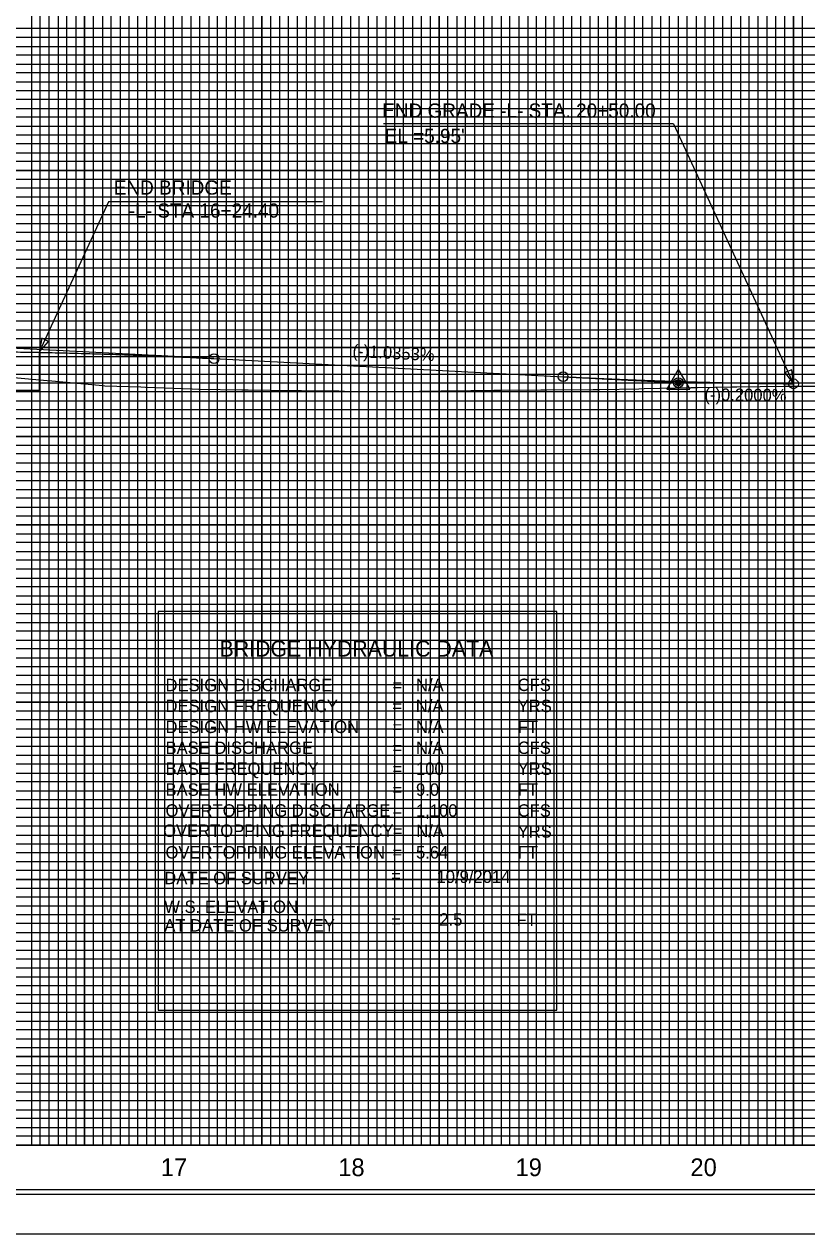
# Model space of a CAD drawing. Extents: x 575424 to 577182, y -52702 to -51602.
# Drawn here: x 576331 to 576773, y -52702 to -52020 of the extents above; entities that cross this region are included whole.
import ezdxf

# ---------------------------------------------------------------- set-up
doc = ezdxf.new("R2010")
doc.units = 0
for name, color, linetype in [('Exist Profile Cell', 7, 'Continuous'), ('Exist Vertical Profile Ground Line', 7, 'Continuous'), ('Exist Vertical Profile Horizontal Axis Label Major', 7, 'Continuous'), ('Prop Grid Mask', 7, 'Continuous'), ('Prop PFL Structure Hydraulic Data Label CELL', 7, 'Continuous'), ('Prop PFL VPI Symbol CELL', 7, 'Continuous'), ('Prop Roadway Bridge', 7, 'Continuous'), ('Prop Vertical Profile Curve Label', 7, 'Continuous'), ('Prop Vertical Profile Ditch Grade Right Label', 7, 'Continuous'), ('Prop Vertical Profile Grade', 7, 'Continuous'), ('Prop Vertical Profile Grade Label', 7, 'Continuous'), ('Prop VPI Label', 7, 'Continuous'), ('Scratch_Level_1', 7, 'Continuous'), ('Sheet Cutting Line CELL', 7, 'Continuous'), ('Sheet DOT Grid CELL', 7, 'Continuous'), ('Sheet Layout Profile Border', 7, 'Continuous'), ('Sheet Plot Border Inside CELL', 7, 'Continuous'), ('Sheet Plot Border Outside CELL', 7, 'Continuous'), ('Sheet Profile CELL', 7, 'Continuous'), ('Sheet Profile Grid Major CELL', 7, 'Continuous'), ('Sheet Profile Grid Middle CELL', 7, 'Continuous'), ('Sheet Profile Grid Minor CELL', 7, 'Continuous')]:
    doc.layers.add(name, color=color, linetype=linetype)

# ---------------------------------------------------------------- blocks, each defined once
blk = doc.blocks.new('Profile VPI Symbol')
at = {"layer": 'Prop PFL VPI Symbol CELL'}
for p, q in [((-0.001, 0.147), (-0.13, -0.077)), ((-0.001, 0.147), (0.129, -0.077)), ((-0.13, -0.077), (0.129, -0.077))]:
    blk.add_line(p, q, dxfattribs=at)
for radius in [0.035, 0.024]:
    blk.add_circle((-0.001, -0.003), radius, dxfattribs=at)

msp = doc.modelspace()

# ---------------------------------------------------------------- linework, layer by layer
at = {"layer": 'Exist Profile Cell'}
msp.add_line((575715.21, -52252.64), (576835.62, -52252.64), dxfattribs=at)
at = {"layer": 'Exist Vertical Profile Ground Line'}
msp.add_lwpolyline([(576320.86, -52218.9), (576344.06, -52221.01), (576346.72, -52221.24), (576373.5, -52223.72), (576376.71, -52224), (576396.98, -52224.67), (576399.6, -52224.8), (576425.87, -52225.66), (576429.6, -52225.85), (576453.87, -52226.28), (576457.56, -52226.27), (576483.52, -52226.74), (576487.56, -52226.72), (576508.6, -52226.9), (576511.77, -52226.96), (576537.83, -52227.18), (576541.77, -52227.24), (576566.33, -52226.88), (576569.94, -52226.84), (576596.12, -52226.45), (576599.94, -52226.4), (576622.54, -52226.27), (576626, -52226.26), (576652.11, -52226.11), (576656, -52226.1), (576677.86, -52225.65), (576680.97, -52225.56), (576707.18, -52225.02), (576710.97, -52224.9), (576730.38, -52224.61), (576733.22, -52224.58), (576759.5, -52224.19), (576763.22, -52224.14), (576788.07, -52224.25)], dxfattribs=at)
at = {"layer": 'Prop Grid Mask'}
msp.add_lwpolyline([(576406.66, -52576.39), (576631.66, -52576.39), (576631.66, -52351.39), (576406.66, -52351.39)], close=True, dxfattribs=at)
at = {"layer": 'Prop Roadway Bridge'}
for p in [(576339.61, -52205.1), (576219.61, -52226.45)]:
    msp.add_line(p, (576339.61, -52226.45), dxfattribs=at)
at = {"layer": 'Prop Vertical Profile Grade'}
msp.add_line((576438.21, -52208.68), (576635.21, -52218.88), dxfattribs=at)
for points in [[(576112.21, -52209), (576118.73, -52208.66), (576125.25, -52208.33), (576131.77, -52208.01), (576138.29, -52207.71), (576144.81, -52207.42), (576151.33, -52207.15), (576157.85, -52206.88), (576164.37, -52206.64), (576170.89, -52206.4), (576177.41, -52206.18), (576183.93, -52205.98), (576190.45, -52205.79), (576196.97, -52205.61), (576203.49, -52205.44), (576210.01, -52205.29), (576216.53, -52205.16), (576223.05, -52205.03), (576229.57, -52204.92), (576236.09, -52204.83), (576242.61, -52204.74), (576249.13, -52204.68), (576255.65, -52204.62), (576262.17, -52204.58), (576268.69, -52204.55), (576275.21, -52204.54), (576281.73, -52204.54), (576288.25, -52204.55), (576294.77, -52204.58), (576301.29, -52204.62), (576307.81, -52204.68), (576314.33, -52204.75), (576320.85, -52204.83), (576327.37, -52204.93), (576333.89, -52205.04), (576340.41, -52205.16), (576346.93, -52205.3), (576353.45, -52205.45), (576359.97, -52205.62), (576366.49, -52205.8), (576373.01, -52205.99), (576379.53, -52206.2), (576386.05, -52206.42), (576392.57, -52206.65), (576399.09, -52206.9), (576405.61, -52207.16), (576412.13, -52207.44), (576418.65, -52207.73), (576425.17, -52208.03), (576431.69, -52208.35), (576438.21, -52208.68)], [(576635.21, -52218.88), (576637.81, -52219.01), (576640.41, -52219.14), (576643.01, -52219.27), (576645.61, -52219.4), (576648.21, -52219.52), (576650.81, -52219.64), (576653.41, -52219.76), (576656.01, -52219.88), (576658.61, -52220), (576661.21, -52220.11), (576663.81, -52220.22), (576666.41, -52220.33), (576669.01, -52220.44), (576671.61, -52220.55), (576674.21, -52220.65), (576676.81, -52220.75), (576679.41, -52220.85), (576682.01, -52220.95), (576684.61, -52221.04), (576687.21, -52221.13), (576689.81, -52221.22), (576692.41, -52221.31), (576695.01, -52221.4), (576697.61, -52221.48), (576700.21, -52221.56), (576702.81, -52221.64), (576705.41, -52221.72), (576708.01, -52221.79), (576710.61, -52221.87), (576713.21, -52221.94), (576715.81, -52222), (576718.41, -52222.07), (576721.01, -52222.13), (576723.61, -52222.2), (576726.21, -52222.26), (576728.81, -52222.31), (576731.41, -52222.37), (576734.01, -52222.42), (576736.61, -52222.47), (576739.21, -52222.52), (576741.81, -52222.57), (576744.41, -52222.61), (576747.01, -52222.65), (576749.61, -52222.7), (576752.21, -52222.73), (576754.81, -52222.77), (576757.41, -52222.8), (576760.01, -52222.83), (576762.61, -52222.86), (576765.21, -52222.89)]]:
    msp.add_spline(points, degree=3, dxfattribs=at)
at = {"layer": 'Prop Vertical Profile Grade Label'}
for p, q in [((576697.41, -52076.2), (576533.9, -52076.2)), ((576499.49, -52120.15), (576378.62, -52120.15))]:
    msp.add_line(p, q, dxfattribs=at)
for points in [[(576697.41, -52076.2), (576765.21, -52222.9)], [(576378.62, -52120.15), (576339.61, -52205.1)]]:
    msp.add_lwpolyline(points, dxfattribs=at)
for points in [[(576340.98, -52197.22), (576339.61, -52205.1), (576344.74, -52198.96)], [(576760.35, -52216.55), (576765.21, -52222.9), (576764.18, -52214.97)]]:
    msp.add_lwpolyline(points, close=True, dxfattribs=at)
at = {"layer": 'Prop VPI Label'}
for p, q in [((576438.21, -52208.68), (576277.96, -52200.38)), ((576635.21, -52218.88), (576697.46, -52222.1)), ((576765.21, -52222.89), (576702.96, -52222.27))]:
    msp.add_line(p, q, dxfattribs=at)
for centre in [(576438.21, -52208.68), (576635.21, -52218.88), (576700.21, -52222.24), (576765.21, -52222.9)]:
    msp.add_circle(centre, 2.75, dxfattribs=at)
at = {"layer": 'Scratch_Level_1'}
msp.add_line((576996.24, -52212.64), (575674.58, -52212.64), dxfattribs=at)
at = {"layer": 'Sheet Cutting Line CELL'}
msp.add_line((575498.21, -52702.49), (577182.21, -52702.49), dxfattribs=at)
at = {"layer": 'Sheet DOT Grid CELL'}
for p, q in [((576365.21, -51627.49), (576365.21, -52652.49)), ((576415.21, -51627.49), (576415.21, -52652.49)), ((576465.21, -51627.49), (576465.21, -52652.49)), ((576515.21, -51627.49), (576515.21, -52652.49)), ((576565.21, -51627.49), (576565.21, -52652.49)), ((576615.21, -51627.49), (576615.21, -52652.49)), ((576665.21, -51627.49), (576665.21, -52652.49)), ((576715.21, -51627.49), (576715.21, -52652.49)), ((576765.21, -51627.49), (576765.21, -52652.49)), ((575665.21, -52052.49), (577165.21, -52052.49)), ((575665.21, -52102.49), (577165.21, -52102.49)), ((575665.21, -52152.49), (577165.21, -52152.49)), ((575665.21, -52202.49), (577165.21, -52202.49)), ((575665.21, -52252.49), (577165.21, -52252.49)), ((575665.21, -52302.49), (577165.21, -52302.49)), ((575665.21, -52352.49), (577165.21, -52352.49)), ((575665.21, -52402.49), (577165.21, -52402.49)), ((575665.21, -52452.49), (577165.21, -52452.49)), ((575665.21, -52502.49), (577165.21, -52502.49)), ((575665.21, -52552.49), (577165.21, -52552.49)), ((575665.21, -52602.49), (577165.21, -52602.49))]:
    msp.add_line(p, q, dxfattribs=at)
at = {"layer": 'Sheet Layout Profile Border'}
msp.add_lwpolyline([(575715.21, -51627.49), (575715.21, -52652.49), (577115.21, -52652.49), (577115.21, -51765.04), (576965.16, -51765.04), (576965.16, -51627.49)], close=True, dxfattribs=at)
at = {"layer": 'Sheet Plot Border Inside CELL'}
msp.add_lwpolyline([(577177.71, -51624.94), (575511.21, -51624.94), (575511.21, -52680.04), (577177.71, -52680.04)], close=True, dxfattribs=at)
at = {"layer": 'Sheet Plot Border Outside CELL'}
msp.add_lwpolyline([(577182.21, -51602.49), (575498.21, -51602.49), (575498.21, -52702.49), (577182.21, -52702.49)], close=True, dxfattribs=at)
at = {"layer": 'Sheet Profile CELL'}
msp.add_line((577165.21, -52652.49), (575665.21, -52652.49), dxfattribs=at)
msp.add_lwpolyline([(577165.21, -51627.49), (575665.21, -51627.49), (575665.21, -52677.49), (577165.21, -52677.49)], close=True, dxfattribs=at)
at = {"layer": 'Sheet Profile Grid Major CELL'}
for points in [[(576315.21, -52652.49), (576365.21, -52652.49), (576365.21, -51627.49)], [(576415.21, -51627.49), (576415.21, -52652.49), (576465.21, -52652.49), (576465.21, -51627.49)], [(576515.21, -51627.49), (576515.21, -52652.49), (576565.21, -52652.49), (576565.21, -51627.49)], [(576615.21, -51627.49), (576615.21, -52652.49), (576665.21, -52652.49), (576665.21, -51627.49)], [(576715.21, -51627.49), (576715.21, -52652.49), (576765.21, -52652.49), (576765.21, -51627.49)], [(577165.21, -52102.49), (575665.21, -52102.49), (575665.21, -52052.49), (577165.21, -52052.49)], [(577165.21, -52202.49), (575665.21, -52202.49), (575665.21, -52152.49), (577165.21, -52152.49)], [(577165.21, -52302.49), (575665.21, -52302.49), (575665.21, -52252.49), (577165.21, -52252.49)], [(577165.21, -52402.49), (575665.21, -52402.49), (575665.21, -52352.49), (577165.21, -52352.49)], [(577165.21, -52502.49), (575665.21, -52502.49), (575665.21, -52452.49), (577165.21, -52452.49)], [(577165.21, -52602.49), (575665.21, -52602.49), (575665.21, -52552.49), (577165.21, -52552.49)]]:
    msp.add_lwpolyline(points, dxfattribs=at)
at = {"layer": 'Sheet Profile Grid Middle CELL'}
for points in [[(576290.21, -52652.49), (576340.21, -52652.49), (576340.21, -51627.49)], [(576390.21, -51627.49), (576390.21, -52652.49), (576440.21, -52652.49), (576440.21, -51627.49)], [(576490.21, -51627.49), (576490.21, -52652.49), (576540.21, -52652.49), (576540.21, -51627.49)], [(576590.21, -51627.49), (576590.21, -52652.49), (576640.21, -52652.49), (576640.21, -51627.49)], [(576690.21, -51627.49), (576690.21, -52652.49), (576740.21, -52652.49), (576740.21, -51627.49)], [(577165.21, -52027.49), (575665.21, -52027.49), (575665.21, -52077.49), (577165.21, -52077.49)], [(577165.21, -52127.49), (575665.21, -52127.49), (575665.21, -52177.49), (577165.21, -52177.49)], [(577165.21, -52227.49), (575665.21, -52227.49), (575665.21, -52277.49), (577165.21, -52277.49)], [(577165.21, -52327.49), (575665.21, -52327.49), (575665.21, -52377.49), (577165.21, -52377.49)], [(577165.21, -52427.49), (575665.21, -52427.49), (575665.21, -52477.49), (577165.21, -52477.49)], [(577165.21, -52527.49), (575665.21, -52527.49), (575665.21, -52577.49), (577165.21, -52577.49)], [(577165.21, -52627.49), (575665.21, -52627.49)]]:
    msp.add_lwpolyline(points, dxfattribs=at)
at = {"layer": 'Sheet Profile Grid Minor CELL'}
for points in [[(576335.21, -51627.49), (576335.21, -52652.49), (576345.21, -52652.49), (576345.21, -51627.49)], [(576350.21, -51627.49), (576350.21, -52652.49), (576355.21, -52652.49), (576355.21, -51627.49)], [(576360.21, -51627.49), (576360.21, -52652.49), (576370.21, -52652.49), (576370.21, -51627.49)], [(576375.21, -51627.49), (576375.21, -52652.49), (576380.21, -52652.49), (576380.21, -51627.49)], [(576385.21, -51627.49), (576385.21, -52652.49), (576395.21, -52652.49), (576395.21, -51627.49)], [(576400.21, -51627.49), (576400.21, -52652.49), (576405.21, -52652.49), (576405.21, -51627.49)], [(576410.21, -51627.49), (576410.21, -52652.49), (576420.21, -52652.49), (576420.21, -51627.49)], [(576425.21, -51627.49), (576425.21, -52652.49)], [(576425.21, -52652.49), (576430.21, -52652.49), (576430.21, -51628.09)], [(576435.21, -51628.09), (576435.21, -52652.49), (576445.21, -52652.49), (576445.21, -51627.49)], [(576450.21, -51627.49), (576450.21, -52652.49), (576455.21, -52652.49), (576455.21, -51627.49)], [(576460.21, -51627.49), (576460.21, -52652.49), (576470.21, -52652.49), (576470.21, -51627.49)], [(576475.21, -51627.49), (576475.21, -52652.49), (576480.21, -52652.49), (576480.21, -51627.49)], [(576485.21, -51627.49), (576485.21, -52652.49), (576495.21, -52652.49), (576495.21, -51627.49)], [(576500.21, -51627.49), (576500.21, -52652.49), (576505.21, -52652.49), (576505.21, -51627.49)], [(576510.21, -51627.49), (576510.21, -52652.49), (576520.21, -52652.49), (576520.21, -51627.49)], [(576525.21, -51627.49), (576525.21, -52652.49), (576530.21, -52652.49), (576530.21, -51627.49)], [(576535.21, -51627.49), (576535.21, -52652.49), (576545.21, -52652.49), (576545.21, -51627.49)], [(576550.21, -51627.49), (576550.21, -52652.49), (576555.21, -52652.49), (576555.21, -51627.49)], [(576560.21, -51627.49), (576560.21, -52652.49), (576570.21, -52652.49), (576570.21, -51627.49)], [(576575.21, -51627.49), (576575.21, -52652.49), (576580.21, -52652.49), (576580.21, -51627.49)], [(576585.21, -51627.49), (576585.21, -52652.49), (576595.21, -52652.49), (576595.21, -51627.49)], [(576600.21, -51627.49), (576600.21, -52652.49), (576605.21, -52652.49), (576605.21, -51627.49)], [(576610.21, -51627.49), (576610.21, -52652.49), (576620.21, -52652.49), (576620.21, -51627.49)], [(576625.21, -51627.49), (576625.21, -52652.49), (576630.21, -52652.49), (576630.21, -51627.49)], [(576635.21, -51627.49), (576635.21, -52652.49), (576645.21, -52652.49), (576645.21, -51627.49)], [(576650.21, -51627.49), (576650.21, -52652.49), (576655.21, -52652.49), (576655.21, -51627.49)], [(576660.21, -51627.49), (576660.21, -52652.49), (576670.21, -52652.49), (576670.21, -51627.49)], [(576675.21, -51627.49), (576675.21, -52652.49), (576680.21, -52652.49), (576680.21, -51627.49)], [(576685.21, -51627.49), (576685.21, -52652.49), (576695.21, -52652.49), (576695.21, -51627.49)], [(576700.21, -51627.49), (576700.21, -52652.49), (576705.21, -52652.49), (576705.21, -51627.49)], [(576710.21, -51627.49), (576710.21, -52652.49), (576720.21, -52652.49), (576720.21, -51627.49)], [(576725.21, -51627.49), (576725.21, -52652.49), (576730.21, -52652.49), (576730.21, -51627.49)], [(576735.21, -51627.49), (576735.21, -52652.49)], [(576735.21, -52652.49), (576745.21, -52652.49), (576745.21, -51627.49)], [(576750.21, -51627.49), (576750.21, -52652.49), (576755.21, -52652.49), (576755.21, -51627.49)], [(576760.21, -51627.49), (576760.21, -52652.49), (576770.21, -52652.49), (576770.21, -51627.49)], [(577115.21, -52022.49), (575715.21, -52022.49), (575715.21, -52032.49), (577115.21, -52032.49)], [(577115.21, -52037.49), (575715.21, -52037.49), (575715.21, -52042.49), (577115.21, -52042.49)], [(577115.21, -52047.49), (575715.21, -52047.49), (575715.21, -52057.49), (577115.21, -52057.49)], [(577115.21, -52062.49), (575715.21, -52062.49), (575715.21, -52067.49), (577115.21, -52067.49)], [(577115.21, -52072.49), (575715.21, -52072.49), (575715.21, -52082.49), (577115.21, -52082.49)], [(577115.21, -52087.49), (575715.21, -52087.49), (575715.21, -52092.49), (577115.21, -52092.49)], [(577115.21, -52097.49), (575715.21, -52097.49), (575715.21, -52107.49), (577115.21, -52107.49)], [(577115.21, -52112.49), (575715.21, -52112.49), (575715.21, -52117.49), (577115.21, -52117.49)], [(577115.21, -52122.49), (575715.21, -52122.49), (575715.21, -52132.49), (577115.21, -52132.49)], [(577115.21, -52137.49), (575715.21, -52137.49), (575715.21, -52142.49), (577115.21, -52142.49)], [(577115.21, -52147.49), (575715.21, -52147.49)], [(575715.21, -52157.49), (577115.21, -52157.49)], [(577115.21, -52162.49), (575715.21, -52162.49), (575715.21, -52167.49), (577115.21, -52167.49)], [(577115.21, -52172.49), (575715.21, -52172.49), (575715.21, -52182.49), (577115.21, -52182.49)], [(577115.21, -52187.49), (575715.21, -52187.49), (575715.21, -52192.49), (577115.21, -52192.49)], [(577115.21, -52197.49), (575715.21, -52197.49), (575715.21, -52207.49), (577115.21, -52207.49)], [(577115.21, -52212.49), (575715.21, -52212.49), (575715.21, -52217.49), (577115.21, -52217.49)], [(577115.21, -52222.49), (575715.21, -52222.49), (575715.21, -52232.49), (577115.21, -52232.49)], [(577115.21, -52237.49), (575715.21, -52237.49), (575715.21, -52242.49), (577115.21, -52242.49)], [(577115.21, -52247.49), (575715.21, -52247.49), (575715.21, -52257.49), (577115.21, -52257.49)], [(577115.21, -52262.49), (575715.21, -52262.49), (575715.21, -52267.49), (577115.21, -52267.49)], [(577115.21, -52272.49), (575715.21, -52272.49), (575715.21, -52282.49), (577115.21, -52282.49)], [(577115.21, -52287.49), (575715.21, -52287.49), (575715.21, -52292.49), (577115.21, -52292.49)], [(577115.21, -52297.49), (575715.21, -52297.49), (575715.21, -52307.49), (577115.21, -52307.49)], [(577115.21, -52312.49), (575715.21, -52312.49), (575715.21, -52317.49), (577115.21, -52317.49)], [(577115.21, -52322.49), (575715.21, -52322.49), (575715.21, -52332.49), (577115.21, -52332.49)], [(577115.21, -52337.49), (575715.21, -52337.49), (575715.21, -52342.49), (577115.21, -52342.49)], [(577115.21, -52347.49), (575715.21, -52347.49), (575715.21, -52357.49), (577115.21, -52357.49)], [(577115.21, -52362.49), (575715.21, -52362.49), (575715.21, -52367.49), (577115.21, -52367.49)], [(577115.21, -52372.49), (575715.21, -52372.49), (575715.21, -52382.49), (577115.21, -52382.49)], [(577115.21, -52387.49), (575715.21, -52387.49), (575715.21, -52392.49), (577115.21, -52392.49)], [(577115.21, -52397.49), (575715.21, -52397.49), (575715.21, -52407.49), (577115.21, -52407.49)], [(577115.21, -52412.49), (575715.21, -52412.49), (575715.21, -52417.49), (577115.21, -52417.49)], [(577115.21, -52422.49), (575715.21, -52422.49), (575715.21, -52432.49), (577115.21, -52432.49)], [(577115.21, -52437.49), (575715.21, -52437.49), (575715.21, -52442.49), (577115.21, -52442.49)], [(577115.21, -52447.49), (575715.21, -52447.49)], [(575715.21, -52457.49), (577115.21, -52457.49)], [(577115.21, -52462.49), (575715.21, -52462.49), (575715.21, -52467.49), (577115.21, -52467.49)], [(577115.21, -52472.49), (575715.21, -52472.49)], [(575715.21, -52482.49), (577115.21, -52482.49)], [(577115.21, -52487.49), (575715.21, -52487.49), (575715.21, -52492.49), (577115.21, -52492.49)], [(577115.21, -52497.49), (575715.21, -52497.49), (575715.21, -52507.49), (577115.21, -52507.49)], [(577115.21, -52512.49), (575715.21, -52512.49), (575715.21, -52517.49), (577115.21, -52517.49)], [(577115.21, -52522.49), (575715.21, -52522.49), (575715.21, -52532.49), (577115.21, -52532.49)], [(577115.21, -52537.49), (575715.21, -52537.49), (575715.21, -52542.49), (577115.21, -52542.49)], [(577115.21, -52547.49), (575715.21, -52547.49), (575715.21, -52557.49), (577115.21, -52557.49)], [(577115.21, -52562.49), (575715.21, -52562.49), (575715.21, -52567.49), (577115.21, -52567.49)], [(577115.21, -52572.49), (575715.21, -52572.49), (575715.21, -52582.49), (577115.21, -52582.49)], [(577115.21, -52587.49), (575715.21, -52587.49), (575715.21, -52592.49), (577115.21, -52592.49)], [(577115.21, -52597.49), (575715.21, -52597.49), (575715.21, -52607.49), (577115.21, -52607.49)], [(577115.21, -52612.49), (575715.21, -52612.49), (575715.21, -52617.49), (577115.21, -52617.49)], [(577115.21, -52622.49), (575715.21, -52622.49), (575715.21, -52632.49), (577115.21, -52632.49)], [(577115.21, -52637.49), (575715.21, -52637.49), (575715.21, -52642.49), (577115.21, -52642.49)], [(577115.21, -52647.49), (575715.21, -52647.49)]]:
    msp.add_lwpolyline(points, dxfattribs=at)

# ---------------------------------------------------------------- block references
at = {"layer": 'Prop Vertical Profile Ditch Grade Right Label', "xscale": 50, "yscale": 50}
msp.add_blockref('Profile VPI Symbol', (576700.25, -52222.11), dxfattribs=at)

# ---------------------------------------------------------------- texts
at = {"layer": 'Exist Vertical Profile Horizontal Axis Label Major'}
for s, p in [('17', (576408.19, -52669.95)), ('18', (576508.32, -52669.95)), ('19', (576608.36, -52669.95)), ('20', (576707.04, -52669.95))]:
    msp.add_text(s, height=10, dxfattribs=at).set_placement(p)
at = {"layer": 'Prop PFL Structure Hydraulic Data Label CELL'}
for s, height, p in [('BRIDGE HYDRAULIC DATA', 9, (576441.34, -52376.81)), ('DESIGN DISCHARGE', 7, (576410.86, -52396.34)), ('=   N/A  ', 7, (576538.93, -52396.34)), ('CFS', 7, (576609.58, -52396.24)), ('DESIGN FREQUENCY', 7, (576410.86, -52408.14)), ('=   N/A   ', 7, (576538.81, -52408.11)), ('YRS', 7, (576609.58, -52408.14)), ('=    ', 7, (576538.93, -52408.14)), ('DESIGN HW ELEVATION', 7, (576410.86, -52419.94)), ('=   N/A   ', 7, (576538.93, -52419.94)), ('FT', 7, (576609.58, -52419.94)), ('BASE DISCHARGE', 7, (576410.86, -52431.74)), ('=   N/A   ', 7, (576538.93, -52431.74)), ('CFS', 7, (576609.58, -52431.74)), ('BASE FREQUENCY', 7, (576410.86, -52443.54)), ('=   100', 7, (576538.93, -52443.54)), ('YRS', 7, (576609.58, -52443.54)), ('BASE HW ELEVATION', 7, (576410.86, -52455.34)), ('=   9.0     ', 7, (576538.93, -52455.34)), ('FT', 7, (576609.58, -52455.34)), ('OVERTOPPING DISCHARGE', 7, (576410.86, -52467.14)), ('=   1,100   ', 7, (576538.93, -52467.14)), ('CFS', 7, (576609.58, -52467.14)), ('OVERTOPPING FREQUENCY', 7, (576409.5, -52478.53)), ('=   N/A   ', 7, (576539.06, -52478.66)), ('YRS', 7, (576609.58, -52478.94)), ('OVERTOPPING ELEVATION', 7, (576410.86, -52490.74)), ('=   5.64', 7, (576538.93, -52490.74)), ('FT', 7, (576609.58, -52490.74)), ('10/9/2014', 7, (576563.78, -52504.55)), ('DATE OF SURVEY', 7, (576410.18, -52505.25)), ('=           ', 7, (576538.25, -52503.95)), ('W.S. ELEVATION', 7, (576410.18, -52521.45)), ('AT DATE OF SURVEY', 7, (576410.18, -52531.95)), ('=         ', 7, (576538.25, -52529.5)), ('2.5', 7, (576565.34, -52528.61)), ('FT', 7, (576608.9, -52528.9))]:
    msp.add_text(s, height=height, dxfattribs=at).set_placement(p)
at = {"layer": 'Prop Vertical Profile Curve Label'}
for s, p in [('END GRADE -L- STA. 20+50.00', (576533.14, -52072.73)), ("EL =5.95'", (576534.5, -52087.03)), ('END BRIDGE ', (576381.68, -52116.15)), ('-L- STA 16+24.40 ', (576390.19, -52129.15))]:
    msp.add_text(s, height=8, dxfattribs=at).set_placement(p)
at = {"layer": 'Prop Vertical Profile Grade Label'}
for s, rotation, p in [('(-)1.0353%', 357.03675, (576516.24, -52207.69)), ('(-)0.2000%', 359.42704, (576714.92, -52232.39))]:
    msp.add_text(s, height=7, rotation=rotation, dxfattribs=at).set_placement(p)

doc.saveas('drawing.dxf')
